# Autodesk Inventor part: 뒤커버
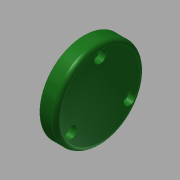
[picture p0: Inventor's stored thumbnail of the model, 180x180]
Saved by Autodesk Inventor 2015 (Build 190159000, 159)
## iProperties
Created: 2015-11
Part Number: 뒤커버
Material: 알루미늄 6061
Document SubType Name: Modeling
Designer: mduedu
Density: 1 g/cm^3
Appearance: 매끄러움 - 짙은 산림 녹색
Author: mduedu
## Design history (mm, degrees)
sketch "스케치5"
  geometry: C1 r 30 at (0, 0); 2 further points
  constraints: 2 coincident, 1 centre point
  dimensions: "d66" = 60 diameter of C1
extrude "돌출2" new body sketch "스케치5" distance "d67" = 11; taper "d68" = 0 deg
sketch "스케치6"
  geometry: C1 r 16 at (0, 0); 1 further point
  constraints: 1 centre point, 1 coincident
  dimensions: "d69" = 32 diameter of C1
extrude "돌출3" join sketch "스케치6" distance "d70" = 3; taper "d71" = 0 deg
hole "구멍5" diameter "d74" = 25; stored, may be unused: countersink angle "d78" = 90 deg, drill point angle "d80" = 0 deg; dims "d72" = 10, "d73" = 10, "d75" = 6, "d76" = 4, "d77" = 2, "d79" = 10
fillet "모깎기8" dims "d82" = 3
fillet "모깎기9" dims "d83" = 3
fillet "모깎기10" dims "d84" = 0.3
sketch "스케치7" dims "d85" = 46
  geometry: 3 further points
  constraints: 2 vertical alignment, 1 coincident, 2 other
hole "구멍6" sketch "스케치7" at (0, 23) diameter "d86" = 4.5; stored, may be unused: countersink angle "d90" = 90 deg, drill point angle "d92" = 0 deg; dims "d87" = 6, "d88" = 8, "d89" = 4.6, "d91" = 10
node "솔리드2"
pattern_circular "원형 패턴3" dims angle "d94" = 360 deg
